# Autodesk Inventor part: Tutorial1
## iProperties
Created: 2005-02
Part Number: Tutorial1
Document SubType Name: Modeling
Designer: CADCIM
Manufacturer: Standard
Standards Organization: Custom
Density: 1 g/cm^3
Author: CADCIM
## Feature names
1. Extrusion1
2. Extrusion2
3. Extrusion3
